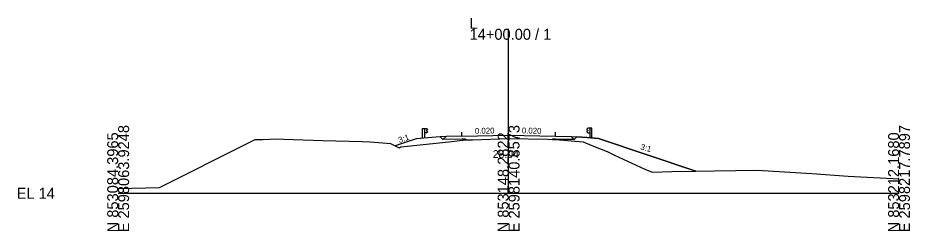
# Model space of a CAD drawing. Extents: x -26 to 1203, y -10 to 9526.
# Drawn here: x -25.7 to 202.8, y 3990.3 to 4044.9 of the extents above; entities that cross this region are included whole.
import ezdxf

# ---------------------------------------------------------------- set-up
doc = ezdxf.new("R2010")
doc.units = 0
for name, color, linetype in [('Exist Cross Section Cell', 7, 'Continuous'), ('Exist XS Center Line Elevation Label', 7, 'Continuous'), ('Exist XS Ground Line', 7, 'Continuous'), ('Prop XS Earthwork Shape', 7, 'Continuous'), ('Prop XS EOT Tick Mark', 7, 'Continuous'), ('Prop XS Finish Grade', 7, 'Continuous'), ('Prop XS Finish Grade Earthwork', 7, 'Continuous'), ('Prop XS Finish Grade Paved Shoulder', 7, 'Continuous'), ('Prop XS Finish Grade Pavement', 7, 'Continuous'), ('Prop XS Guardrail', 7, 'Continuous'), ('Prop XS Pvmt Edge Slope', 7, 'Continuous'), ('Prop XS SE Text', 7, 'Continuous'), ('Prop XS Side Slope Text', 7, 'Continuous'), ('Prop XS Subgrade Earthwork', 7, 'Continuous')]:
    doc.layers.add(name, color=color, linetype=linetype)

msp = doc.modelspace()

# ---------------------------------------------------------------- linework, layer by layer
at = {"layer": 'Exist Cross Section Cell'}
for p, q in [((100, 4000), (100, 4042.11)), ((0, 4000), (100, 4000)), ((100, 4000), (200, 4000))]:
    msp.add_line(p, q, dxfattribs=at)
at = {"layer": 'Exist XS Ground Line'}
for p, q in [((33.23, 4012.82), (35.07, 4013.74)), ((35.07, 4013.74), (37.07, 4013.8)), ((37.07, 4013.8), (40.43, 4013.9)), ((40.43, 4013.9), (42.43, 4013.84)), ((42.43, 4013.84), (52.46, 4013.54)), ((52.46, 4013.54), (62.49, 4013.23)), ((62.49, 4013.23), (64.49, 4013.17)), ((64.49, 4013.17), (67.77, 4012.91)), ((72.42, 4011.9), (84.69, 4013.21)), ((84.69, 4013.21), (88.97, 4013.65)), ((88.97, 4013.65), (90.75, 4013.71)), ((90.75, 4013.71), (100.08, 4014.04)), ((100.08, 4014.04), (110.08, 4013.82)), ((110.08, 4013.82), (111.25, 4013.8)), ((111.25, 4013.8), (112.01, 4013.74)), ((112.01, 4013.74), (119.1, 4013.19)), ((119.1, 4013.19), (121.28, 4012.25)), ((10.55, 4001.48), (33.23, 4012.82)), ((67.77, 4012.91), (69.77, 4012.75)), ((69.77, 4012.75), (71.84, 4011.72)), ((71.84, 4011.72), (71.99, 4011.64)), ((71.99, 4011.64), (72.42, 4011.9)), ((121.28, 4012.25), (125.27, 4010.68)), ((125.27, 4010.68), (127.13, 4009.79)), ((127.13, 4009.79), (134.87, 4006.19)), ((134.87, 4006.19), (136.77, 4005.43)), ((136.77, 4005.43), (141.82, 4005.62)), ((141.82, 4005.62), (163.67, 4005.89)), ((163.67, 4005.89), (177.65, 4005.07)), ((177.65, 4005.07), (186.96, 4004.41)), ((186.96, 4004.41), (200, 4003.71)), ((0, 4001.21), (10.55, 4001.48))]:
    msp.add_line(p, q, dxfattribs=at)
at = {"layer": 'Prop XS Earthwork Shape'}
for points in [[(82.5, 4014.46), (79.29, 4014.2), (76.29, 4013.96), (70.93, 4012.17), (71.84, 4011.72), (71.99, 4011.64), (72.42, 4011.9), (84.69, 4013.21), (88.97, 4013.66), (88.97, 4013.88), (88, 4013.86), (83.19, 4013.77)], [(111.25, 4013.88), (111.25, 4013.79), (112.01, 4013.74), (119.1, 4013.19), (121.28, 4012.25), (125.27, 4010.68), (127.13, 4009.79), (134.87, 4006.19), (136.77, 4005.43), (141.82, 4005.62), (147.97, 4005.69), (123.01, 4014.02), (120, 4014.26), (117.5, 4014.46), (116.81, 4013.77), (112, 4013.86)]]:
    msp.add_lwpolyline(points, close=True, dxfattribs=at)
at = {"layer": 'Prop XS EOT Tick Mark'}
for p, q in [((88, 4014.66), (88, 4015.66)), ((112, 4014.66), (112, 4015.66))]:
    msp.add_line(p, q, dxfattribs=at)
at = {"layer": 'Prop XS Finish Grade'}
for p, q in [((84, 4014.58), (82.5, 4014.46)), ((116, 4014.58), (117.5, 4014.46))]:
    msp.add_line(p, q, dxfattribs=at)
at = {"layer": 'Prop XS Finish Grade Earthwork'}
for p, q in [((76.29, 4013.96), (70.93, 4012.17)), ((79.29, 4014.2), (76.29, 4013.96)), ((82.5, 4014.46), (79.29, 4014.2)), ((117.5, 4014.46), (120, 4014.26)), ((120, 4014.26), (123.01, 4014.02)), ((123.01, 4014.02), (147.97, 4005.69))]:
    msp.add_line(p, q, dxfattribs=at)
at = {"layer": 'Prop XS Finish Grade Paved Shoulder'}
for p, q in [((88, 4014.66), (84, 4014.58)), ((112, 4014.66), (116, 4014.58))]:
    msp.add_line(p, q, dxfattribs=at)
at = {"layer": 'Prop XS Finish Grade Pavement'}
for p, q in [((88, 4014.66), (100, 4014.9)), ((100, 4014.9), (112, 4014.66))]:
    msp.add_line(p, q, dxfattribs=at)
at = {"layer": 'Prop XS Guardrail'}
for p, q in [((77.97, 4016.59), (78.47, 4016.59)), ((77.97, 4014.09), (77.97, 4016.59)), ((78.47, 4016.59), (78.97, 4016.59)), ((78.47, 4016.59), (78.47, 4014.09)), ((78.97, 4015.46), (78.47, 4015.46)), ((78.97, 4016.59), (79.26, 4016.39)), ((79.26, 4016.27), (78.97, 4016.07)), ((78.97, 4016.07), (78.97, 4015.98)), ((78.97, 4015.98), (79.26, 4015.78)), ((79.26, 4015.66), (78.97, 4015.46)), ((79.26, 4016.39), (79.29, 4016.33)), ((79.29, 4016.33), (79.26, 4016.27)), ((79.26, 4015.78), (79.29, 4015.72)), ((79.29, 4015.72), (79.26, 4015.66)), ((120.04, 4016.45), (120.01, 4016.39)), ((120.01, 4016.39), (120.04, 4016.33)), ((120.04, 4015.84), (120.01, 4015.78)), ((120.01, 4015.78), (120.04, 4015.72)), ((120.33, 4016.65), (120.04, 4016.45)), ((120.04, 4016.33), (120.33, 4016.13)), ((120.33, 4016.04), (120.04, 4015.84)), ((120.04, 4015.72), (120.33, 4015.52)), ((120.83, 4016.65), (120.33, 4016.65)), ((120.33, 4016.13), (120.33, 4016.04)), ((120.33, 4015.52), (120.83, 4015.52)), ((121.33, 4016.65), (120.83, 4016.65)), ((120.83, 4016.65), (120.83, 4014.15)), ((121.33, 4014.15), (121.33, 4016.65))]:
    msp.add_line(p, q, dxfattribs=at)
at = {"layer": 'Prop XS Pvmt Edge Slope'}
for p, q in [((84, 4014.58), (83.19, 4013.77)), ((116, 4014.58), (116.81, 4013.77))]:
    msp.add_line(p, q, dxfattribs=at)
at = {"layer": 'Prop XS Subgrade Earthwork'}
for p, q in [((83.19, 4013.77), (82.5, 4014.46)), ((88, 4013.86), (83.19, 4013.77)), ((88.97, 4013.88), (88, 4013.86)), ((88.97, 4013.88), (88.97, 4013.66)), ((111.25, 4013.88), (111.25, 4013.79)), ((111.25, 4013.88), (112, 4013.86)), ((112, 4013.86), (116.81, 4013.77)), ((116.81, 4013.77), (117.5, 4014.46))]:
    msp.add_line(p, q, dxfattribs=at)

# ---------------------------------------------------------------- texts
at = {"layer": 'Exist Cross Section Cell'}
for s, p in [('L', (90, 4042.11)), ('14+00.00 / 1', (90, 4039.31)), ('EL 14', (-26, 3998.6))]:
    msp.add_text(s, height=2.8, dxfattribs=at).set_placement(p)
for s, p in [('N 853084.3965', (0, 3990)), ('E 2598063.9248', (2.8, 3990)), ('N 853148.2822', (100, 3990)), ('E 2598140.8573', (102.8, 3990)), ('N 853212.1680', (200, 3990)), ('E 2598217.7897', (202.8, 3990))]:
    msp.add_text(s, height=2.8, rotation=90, dxfattribs=at).set_placement(p)
at = {"layer": 'Exist XS Center Line Elevation Label'}
msp.add_text('28.04', height=2, dxfattribs=at).set_placement((95.93, 4009.04))
at = {"layer": 'Prop XS SE Text'}
for rotation, p in [(1.1458, (91.38, 4015.22)), (358.8542, (103.38, 4015.33))]:
    msp.add_text('0.020', height=1.5, rotation=rotation, dxfattribs=at).set_placement(p)
at = {"layer": 'Prop XS Side Slope Text'}
for rotation, p in [(18.4349, (72.04, 4012.86)), (345.9638, (133.65, 4011.22))]:
    msp.add_text('3:1', height=1.5, rotation=rotation, dxfattribs=at).set_placement(p)

doc.saveas('drawing.dxf')
